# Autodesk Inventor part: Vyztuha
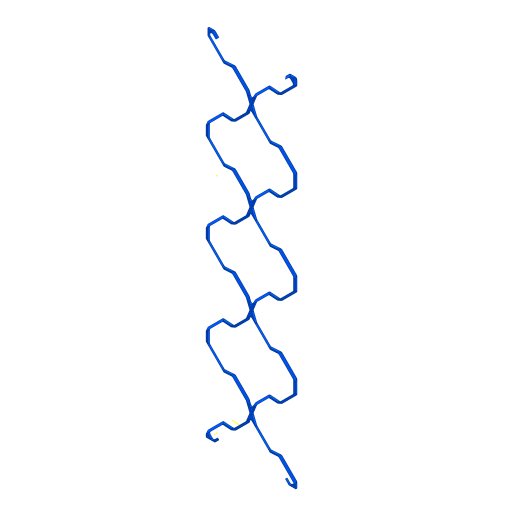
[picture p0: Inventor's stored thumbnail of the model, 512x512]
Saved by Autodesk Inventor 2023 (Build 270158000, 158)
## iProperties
Created: 2025-03
Part Number: Vyztuha
Material: Všeobecné
Document SubType Name: Modeling
Designer: tomik
Density: 1 g/cm^3
Appearance: Výchozí(1)
Author: tomik
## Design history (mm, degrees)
sketch "Náčrt1"
  geometry: L1 (0, 0)-(211.67, 0); L2 (0, 0)-(200, 200)
  constraints: 4 end point, 1 horizontal
  dimensions: "d1" = 45 deg angle of L1 L2; "d2" = 200 distance from line of L2.end L1
node "Pracovní rovina2"
sketch "Náčrt2"
  geometry: L1 (0, 0)-(0, 13.004); L2 (0, 0)-(-15.85, 0); L3 (0, 0)-(-4, 0); L4 (-3.268, 0.732)-(0, 4); L5 (0, 0)-(15.85, 0); L6 (0, 0)-(4, 0); L7 (3.268, 0.732)-(0, 4); L8 (0, 0)-(15.85, 0); L9 (5.036, 0)-(-5.036, 0); A1 r 2.5 centre (-5.036, 2.5) between (-5.036, 0) and (-3.268, 0.732); A2 r 2.5 centre (5.036, 2.5) between (3.268, 0.732) and (5.036, 0); 2 further points
  constraints: 18 end point, 5 point on line, 5 symmetric about line, 4 point on circle, 4 tangent, 2 centre point, 1 collinear, 1 horizontal, 1 vertical, 1 other
  dimensions: "d3" = 4 distance of L1.start L3.end; "d4" = 4 distance of L4.end L1.start; "d5" = 5 diameter of A1; "d6" = 5.03553 distance from line of L9.end L1
extrude "Vysunutí1" new body sketch "Náčrt2" distance "d7" = 200; taper "d8" = 0 deg
node "Pracovní rovina6"
fillet "Zaoblení3" dims "d14" = 2
mirror "Zrcadlit3"
node "Pracovní rovina10"
  node "Pracovní rovina9"
node "Pracovní rovina11"
pattern_linear "Obdélníkové pole1"
sketch "Náčrt3"
  geometry: 1 further point
sketch "Náčrt4"
  geometry: L1 (-30.32, -10.071)-(-30.32, 0) reference; L2 (-30.32, 0)-(0, 0) reference; L3 (10.071, -40.391)-(10.071, -10.071) reference; L4 (0, -40.391)-(10.071, -40.391) reference; L5 (-30.32, -3.621)-(-30.32, -6.45) reference; L6 (-30.32, -5.036)-(5.036, -40.391); L7 (-30.32, -5.036)-(111.102, 136.386); L8 (111.102, 136.386)-(146.457, 101.03); L9 (146.457, 101.03)-(5.036, -40.391); L10 (40.391, 415.738)-(-248.096, 101.03); L11 (-248.096, 101.03)-(128.779, -294.975); L12 (128.779, -294.975)-(406.838, 40.162); L13 (406.838, 40.162)-(40.391, 415.738); 7 further points
  constraints: 16 end point, 2 perpendicular, 1 coincident, 1 midpoint
  dimensions: "d23" = 200 distance of L6.start L7.end; "d24" = 50 distance of L7.end L8.end
extrude "Vysunutí2" cut sketch "Náčrt4" distance "d25" = 200; taper "d26" = 0 deg
fillet "Zaoblení5" dims "d27" = 1
fillet "Zaoblení6" dims "d28" = 1
sketch "Náčrt5"
  geometry: L1 (3.268, 0.732)-(1.414, 2.586) reference; L2 (0, 0)-(0, 7.359); L3 (0, 0)-(6.319, 0); L4 (5.036, 0)-(-5.036, 0) reference; L5 (1.8, 1.2)-(2.8, 1.2); L6 (2.8, 1.2)-(2.8, 2.2); L7 (2.8, 2.2)-(1.8, 2.2); L8 (1.8, 2.2)-(1.8, 1.2); 3 further points
  constraints: 12 end point, 2 parallel, 1 collinear, 1 horizontal, 1 midpoint, 1 perpendicular, 1 vertical
  dimensions: "d30" = 2.8 distance between parallel lines of L6 L2; "d31" = 1.2 distance between parallel lines of L5 L3; "d32" = 1 distance between parallel lines of L6 L8; "d33" = 1 distance from line of L7 point (2.3, 1.2)
extrude "Vysunutí3" cut sketch "Náčrt5" distance "d34" = 15; taper "d35" = 0 deg
node "Pracovní rovina14"
node "Pracovní rovina16"
  node "Pracovní rovina15"
pattern_linear "Obdélníkové pole2" dims "d40" = 50
mirror "Zrcadlit6"
node "Pracovní rovina19"
mirror "Zrcadlit7"
node "Pracovní rovina21"
sketch "Náčrt9"
  geometry: L1 (-50, 1.2)-(-50, 2.2) reference; L2 (-50, 2.2)-(-40.666, 2.2) reference; L3 (-50, 1.2)-(-40.666, 1.2) reference; L4 (-49, 2.2)-(-49, 1.2); 1 further point
  constraints: 2 end point, 2 point on line, 1 perpendicular
  dimensions: "d47" = 1 distance between parallel lines of L4 L1
extrude "Vysunutí5" cut sketch "Náčrt9" stored distance "d48" = 10; taper "d49" = 0 deg
mirror "Zrcadlit8"
node "Pracovní rovina22"
mirror "Zrcadlit9"
node "Pracovní rovina23"
mirror "Zrcadlit11"
sketch "Náčrt10"
  geometry: L1 (-1.8, 1.2)-(-2.8, 1.2); L2 (-2.8, 1.2)-(-2.8, 2.2); L3 (-2.8, 2.2)-(-1.8, 2.2); L4 (-1.8, 2.2)-(-1.8, 1.2); L5 (-5.036, 0)-(5.036, 0) reference; L6 (0, 0)-(0, 4.936); L7 (0, 0)-(-0.148, 0); 1 further point
  constraints: 12 end point, 2 parallel, 1 horizontal, 1 midpoint, 1 perpendicular, 1 point on line, 1 vertical
  dimensions: "d55" = 1.2 distance between parallel lines of L5 L1; "d56" = 1.8 distance between parallel lines of L4 L6; "d57" = 1 distance between parallel lines of L2 L4; "d58" = 1 distance between parallel lines of L3 L1
extrude "Vysunutí6" cut sketch "Náčrt10" distance "d59" = 32; taper "d60" = 0 deg
sketch "Náčrt11"
  geometry: 1 further point
mirror "Zrcadlit12"
sketch "Náčrt12"
  geometry: 1 further point
node "Pracovní rovina25"
mirror "Zrcadlit13"
fillet "Zaoblení7" dims "d70" = 1
node "Pracovní rovina31"
sketch "Náčrt20"
  geometry: L1 (0, 0)-(-7.595, 0); L2 (-1.2, -1.8)-(-1.2, -2.8) reference; L3 (-2.2, -1.8)-(-1.2, -1.8) reference; L4 (-1.2, 1.8)-(-1.2, 2.8); L5 (-2.2, 1.8)-(-1.2, 1.8); L6 (-2.586, 1.414)-(-0.732, 3.268) reference
  constraints: 6 end point, 3 symmetric about line, 1 horizontal
extrude "Vysunutí12" cut sketch "Náčrt20" distance "d79" = 11; taper "d80" = 0 deg
mirror "Zrcadlit15"
pattern_linear "Obdélníkové pole3" dims "d83" = 50
mirror "Zrcadlit16"
sketch "Náčrt23"
  geometry: 1 further point
sketch "Náčrt24"
  geometry: L1 (1.293, 53.838)-(8.627, 61.172) reference; L2 (8.627, 62.587)-(9.127, 62.087) reference; L3 (8.627, 61.172)-(9.334, 61.879); L4 (8.834, 61.379)-(1.293, 53.838) reference; L5 (9.334, 61.879)-(9.127, 62.087); L6 (8.627, 62.587)-(8.627, 61.172); 1 further point
  constraints: 6 end point, 1 collinear, 1 perpendicular, 1 vertical
extrude "Vysunutí14" cut sketch "Náčrt24" stored distance "d89" = 15; taper "d90" = 0 deg
node "Pracovní rovina32"
mirror "Zrcadlit18"
mirror "Zrcadlit19"
sketch "Náčrt25"
  geometry: L1 (9.334, 11.879)-(8.627, 12.587) reference; L2 (15.415, 11.455)-(14.708, 12.162) reference; L3 (9.334, 11.879)-(15.415, 11.455); L4 (8.627, 12.587)-(14.708, 12.162); L5 (22.486, 19.94)-(23.193, 19.233) reference; L6 (26.807, 30.767)-(34.585, 38.545) reference; L7 (22.486, 19.94)-(26.807, 30.767); L8 (35.292, 37.838)-(27.514, 30.06) reference; L9 (23.193, 19.233)-(27.514, 30.06); L10 (27.514, 30.06)-(26.807, 30.767) reference; L11 (35.292, 37.838)-(34.585, 38.545) reference; L12 (41.373, 37.413)-(40.666, 38.121) reference; L13 (35.292, 37.838)-(41.373, 37.413); L14 (34.585, 38.545)-(40.666, 38.121); 1 further point
  constraints: 12 end point
extrude "Vysunutí15" cut sketch "Náčrt25" stored distance "d92" = 10; taper "d93" = 0 deg
mirror "Zrcadlit20"
pattern_linear "Obdélníkové pole5"
fillet "Zaoblení9" dims "d97" = 1
pattern_linear "Obdélníkové pole6" dims "d100" = 50
sketch "Náčrt26"
  geometry: L1 (9.788, -134.193)-(15.415, -134.585) reference; 1 further point
sketch "Náčrt27"
  geometry: L1 (1.8, 1.2)-(2.8, 1.2) reference; L2 (1.8, 2.2)-(1.8, 1.2) reference; L3 (2.8, 1.2)-(1.414, 2.586) reference; L4 (0, 0)-(0, 4); L5 (-1.8, 1.2)-(-2.8, 1.2); L6 (-1.8, 2.2)-(-1.8, 1.2); L7 (-2.8, 1.2)-(-1.414, 2.586)
  constraints: 8 end point, 4 symmetric about line, 1 vertical
extrude "Vysunutí16" cut sketch "Náčrt27" distance "d101" = 6; taper "d102" = 0 deg
sketch "Náčrt28"
  geometry: L1 (0, 0)-(0, 1) reference; L2 (-4.2, 0)-(-1, 0) reference; L3 (0, 0)-(-1, 0); L4 (-1, 0)-(-1, 1); L5 (0, 1)-(-4.2, 1) reference; L6 (-1, 1)-(1.901, 1); L7 (1.901, 1)-(1.901, 0); L8 (1.901, 0)-(0, 0); 2 further points
  constraints: 10 end point, 3 perpendicular, 2 point on line, 1 collinear, 1 horizontal
extrude "Vysunutí17" cut sketch "Náčrt28" distance "d104" = 6; taper "d105" = 0 deg
fillet "Zaoblení10" dims "d106" = 1
mirror "Zrcadlit21"
mirror "Zrcadlit22"
fillet "Zaoblení11" dims "d107" = 1
fillet "Zaoblení12" dims "d108" = 1
sketch "Náčrt31"
  geometry: L1 (48.707, 153.838)-(40.666, 161.879) reference; L2 (49, 153.131)-(49, 146.869) reference; L3 (48.707, 146.162)-(40.666, 138.121) reference; L4 (40.666, 138.121)-(34.585, 138.545) reference; L5 (26.807, 130.767)-(34.585, 138.545) reference; L6 (26.807, 130.767)-(25.929, 128.566) reference; L7 (23.193, 130.767)-(24.071, 128.566) reference; L8 (15.415, 138.545)-(23.193, 130.767) reference; L9 (9.334, 138.121)-(15.415, 138.545) reference; L10 (1.293, 146.162)-(9.334, 138.121) reference; L11 (1, 153.131)-(1, 146.869) reference; L12 (1.293, 153.838)-(9.334, 161.879) reference; L13 (9.334, 161.879)-(15.415, 161.455) reference; L14 (23.193, 169.233)-(15.415, 161.455) reference; L15 (23.193, 169.233)-(24.071, 171.434) reference; L16 (26.807, 169.233)-(25.929, 171.434) reference; L17 (34.585, 161.455)-(26.807, 169.233) reference; L18 (40.666, 161.879)-(34.585, 161.455) reference; L19 (40.666, 61.879)-(34.585, 61.455) reference; L20 (48.707, 53.838)-(40.666, 61.879) reference; L21 (49, 46.869)-(49, 53.131) reference; L22 (48.707, 46.162)-(40.988, 38.443) reference; L23 (40.212, 38.152)-(34.585, 38.545) reference; L24 (26.807, 30.767)-(34.585, 38.545) reference; L25 (26.807, 30.767)-(25.929, 28.566) reference; L26 (23.193, 30.767)-(24.071, 28.566) reference; L27 (15.415, 38.545)-(23.193, 30.767) reference; L28 (9.788, 38.152)-(15.415, 38.545) reference; L29 (1.293, 46.162)-(9.012, 38.443) reference; L30 (1, 46.869)-(1, 53.131) reference; L31 (1.293, 53.838)-(9.334, 61.879) reference; L32 (9.334, 61.879)-(15.415, 61.455) reference; L33 (23.193, 69.233)-(15.415, 61.455) reference; L34 (23.193, 69.233)-(24.071, 71.434) reference; L35 (26.807, 69.233)-(25.929, 71.434) reference; L36 (34.585, 61.455)-(26.807, 69.233) reference; L37 (40.666, 111.879)-(34.585, 111.455) reference; L38 (48.707, 103.838)-(40.666, 111.879) reference; L39 (49, 103.131)-(49, 96.869) reference; L40 (48.707, 96.162)-(40.666, 88.121) reference; L41 (40.666, 88.121)-(34.585, 88.545) reference; L42 (26.807, 80.767)-(34.585, 88.545) reference; L43 (26.807, 80.767)-(25.929, 78.566) reference; L44 (23.193, 80.767)-(24.071, 78.566) reference; L45 (15.415, 88.545)-(23.193, 80.767) reference; L46 (9.334, 88.121)-(15.415, 88.545) reference; L47 (1.293, 96.162)-(9.334, 88.121) reference; L48 (1, 103.131)-(1, 96.869) reference; L49 (1.293, 103.838)-(9.334, 111.879) reference; L50 (9.334, 111.879)-(15.415, 111.455) reference; L51 (23.193, 119.233)-(15.415, 111.455) reference; L52 (23.193, 119.233)-(24.071, 121.434) reference; L53 (26.807, 119.233)-(25.929, 121.434) reference; L54 (34.585, 111.455)-(26.807, 119.233) reference; L55 (35.292, 162.162)-(41.373, 162.587) reference; L56 (35.292, 162.162)-(27.514, 169.94) reference; L57 (25.643, 174.629)-(27.514, 169.94) reference; L58 (25.643, 175.371)-(27.514, 180.06) reference; L59 (35.292, 187.838)-(27.514, 180.06) reference; L60 (35.292, 187.838)-(41.373, 187.413) reference; L61 (50, 196.04)-(41.373, 187.413) reference; L62 (50, 199)-(50, 196.04) reference; L63 (46.04, 200)-(49, 200) reference; L64 (43.777, 197.737)-(46.04, 200) reference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; A1 r 1 centre (48, 153.131) between (49, 153.131) and (48.707, 153.838) reference; A2 r 1 centre (48, 146.869) between (48.707, 146.162) and (49, 146.869) reference; A3 r 1 centre (25, 128.937) between (24.071, 128.566) and (25.929, 128.566) reference; A4 r 1 centre (2, 146.869) between (1, 146.869) and (1.293, 146.162) reference; A5 r 1 centre (2, 153.131) between (1.293, 153.838) and (1, 153.131) reference; A6 r 1 centre (25, 171.063) between (25.929, 171.434) and (24.071, 171.434) reference; A7 r 1 centre (48, 53.131) between (49, 53.131) and (48.707, 53.838) reference; A8 r 1 centre (48, 46.869) between (48.707, 46.162) and (49, 46.869) reference; A9 r 1 centre (40.281, 39.15) between (40.212, 38.152) and (40.988, 38.443) reference; A10 r 1 centre (25, 28.937) between (24.071, 28.566) and (25.929, 28.566) reference; A11 r 1 centre (9.719, 39.15) between (9.012, 38.443) and (9.788, 38.152) reference; A12 r 1 centre (2, 46.869) between (1, 46.869) and (1.293, 46.162) reference; A13 r 1 centre (2, 53.131) between (1.293, 53.838) and (1, 53.131) reference; A14 r 1 centre (25, 71.063) between (25.929, 71.434) and (24.071, 71.434) reference; A15 r 1 centre (48, 103.131) between (49, 103.131) and (48.707, 103.838) reference; A16 r 1 centre (48, 96.869) between (48.707, 96.162) and (49, 96.869) reference; A17 r 1 centre (25, 78.937) between (24.071, 78.566) and (25.929, 78.566) reference; A18 r 1 centre (2, 96.869) between (1, 96.869) and (1.293, 96.162) reference; A19 r 1 centre (2, 103.131) between (1.293, 103.838) and (1, 103.131) reference; A20 r 1 centre (25, 121.063) between (25.929, 121.434) and (24.071, 121.434) reference; A21 r 1 centre (26.571, 175) between (25.643, 175.371) and (25.643, 174.629) reference; A22 r 1 centre (49, 199) between (50, 199) and (49, 200) reference; A23 r 1 centre (46.747, 197.879) between (47.454, 198.586) and (46.04, 198.586) reference; A24 r 1 centre (47.879, 196.747) between (48.586, 196.04) and (48.586, 197.454) reference; A25 r 1 centre (25, 178.937) between (24.071, 178.566) and (25.929, 178.566) reference; A26 r 1 centre (2.121, 196.747) between (1.414, 197.454) and (1.414, 196.04) reference; A27 r 1 centre (3.253, 197.879) between (3.96, 198.586) and (2.546, 198.586) reference; A28 r 1 centre (1, 199) between (1, 200) and (0, 199) reference; A29 r 1 centre (23.429, 175) between (24.357, 174.629) and (24.357, 175.371) reference; A30 r 1 centre (23.429, 125) between (24.357, 124.629) and (24.357, 125.371) reference; A31 r 1 centre (23.429, 75) between (24.357, 74.629) and (24.357, 75.371) reference; A32 r 1 centre (23.429, 25) between (24.357, 24.629) and (24.357, 25.371) reference; A33 r 1 centre (21.633, 20.502) between (22.341, 19.795) and (22.562, 20.131) reference; A34 r 1 centre (14.323, 13.192) between (14.253, 12.194) and (15.03, 12.484) reference; A35 r 1 centre (1, 1) between (0, 1) and (1, 0) reference; A36 r 1 centre (3.253, 2.121) between (2.546, 1.414) and (3.96, 1.414) reference; A37 r 1 centre (2.121, 3.253) between (1.414, 3.96) and (1.414, 2.546) reference; A38 r 1 centre (9.719, 10.85) between (9.788, 11.848) and (9.012, 11.557) reference; A39 r 1 centre (25, 21.063) between (25.929, 21.434) and (24.071, 21.434) reference; A40 r 1 centre (40.281, 10.85) between (40.988, 11.557) and (40.212, 11.848) reference; A41 r 1 centre (46.747, 2.121) between (46.04, 1.414) and (47.454, 1.414) reference; A42 r 1 centre (49, 1) between (49, 0) and (50, 1) reference; A43 r 1 centre (35.677, 13.192) between (34.97, 12.484) and (35.747, 12.194) reference; A44 r 1 centre (28.367, 20.502) between (27.438, 20.131) and (27.659, 19.795) reference; A45 r 1 centre (26.571, 25) between (25.643, 25.371) and (25.643, 24.629) reference; A46 r 1 centre (28.367, 29.498) between (27.659, 30.205) and (27.438, 29.869) reference; A47 r 1 centre (35.677, 36.808) between (35.747, 37.806) and (34.97, 37.516) reference; A48 r 1 centre (26.571, 75) between (25.643, 75.371) and (25.643, 74.629) reference; A49 r 1 centre (26.571, 125) between (25.643, 125.371) and (25.643, 124.629) reference; 1 further point
extrude "Vysunutí18" new body sketch "Náčrt31" distance "d109" = 1; taper "d110" = 0 deg
fillet "Zaoblení13" dims "d111" = 1
fillet "Zaoblení14" dims "d112" = 1
chamfer "Zkosení1" distance "d113" = 1; stored, may be unused: second distance "d114" = 2, angle "d115" = 45 deg
node "Těleso1"
node "Pracovní rovina24"
node "Pracovní rovina26"
node "Pracovní rovina33"
node "Pracovní rovina34"
node "Pracovní rovina35"
node "Pracovní rovina36"
node "Pracovní rovina37"
node "Pracovní rovina38"
node "Pracovní rovina39"
node "Promítnutá smyčka2"
node "Těleso2"
other parameters: "d11" = 25, "d18" = 25, "d50" = 25, "d51" = 25, "d63" = 5, "d78" = -4
